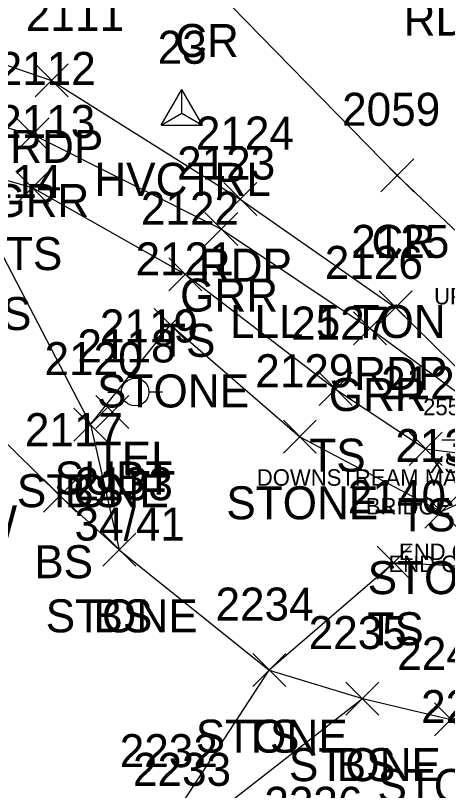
# Model space of a CAD drawing. Extents: x 1459992 to 1461532, y 647785 to 648535.
# Drawn here: x 1461256.61 to 1461282.8, y 648190.36 to 648237.31 of the extents above; entities that cross this region are included whole.
import ezdxf

# ---------------------------------------------------------------- set-up
doc = ezdxf.new("R2010")
doc.units = 0
for name, color, linetype in [('B_A', 7, 'Continuous'), ('B_C', 7, 'Continuous'), ('B_I', 7, 'Continuous'), ('B_TIC', 7, 'Continuous'), ('C_A', 7, 'Continuous'), ('C_I', 7, 'Continuous'), ('CPSM', 7, 'Continuous'), ('L_A', 7, 'Continuous'), ('L_I', 7, 'Continuous'), ('L_TIC', 7, 'Continuous'), ('LASF', 7, 'Continuous'), ('LELB', 7, 'Continuous'), ('P_A', 7, 'Continuous'), ('P_I', 7, 'Continuous'), ('P_TIC', 7, 'Continuous'), ('PET', 7, 'Continuous'), ('PRC', 7, 'Continuous'), ('R_A', 7, 'Continuous'), ('R_I', 7, 'Continuous'), ('R_TIC', 7, 'Continuous'), ('RGR', 7, 'Continuous'), ('S_C', 7, 'Continuous'), ('U_A', 7, 'Continuous'), ('U_C', 7, 'Continuous'), ('U_I', 7, 'Continuous'), ('U_TIC', 7, 'Continuous'), ('UP', 7, 'Continuous')]:
    doc.layers.add(name, color=color, linetype=linetype)

msp = doc.modelspace()

# ---------------------------------------------------------------- linework, layer by layer
at = {"layer": 'B_TIC'}
msp.add_lwpolyline([(1461282.453, 648211.596), (1461283.453, 648211.596)], dxfattribs=at)
at = {"layer": 'CPSM'}
for p, q in [((1461265.443, 648230.661), (1461266.693, 648232.827)), ((1461267.943, 648230.661), (1461266.693, 648232.827)), ((1461266.693, 648231.383), (1461266.693, 648232.827)), ((1461265.443, 648230.661), (1461266.693, 648231.383)), ((1461266.693, 648231.383), (1461266.693, 648231.383)), ((1461266.693, 648231.383), (1461267.943, 648230.661)), ((1461265.443, 648230.661), (1461267.943, 648230.661))]:
    msp.add_line(p, q, dxfattribs=at)
at = {"layer": 'L_TIC'}
for points in [[(1461256.622, 648225.885), (1461258.622, 648227.885)], [(1461258.622, 648225.885), (1461256.622, 648227.885)], [(1461265.905, 648220.633), (1461267.905, 648222.633)], [(1461267.905, 648220.633), (1461265.905, 648222.633)], [(1461265.013, 648217.565), (1461267.013, 648219.565)], [(1461267.013, 648217.565), (1461265.013, 648219.565)], [(1461275.015, 648213.676), (1461277.015, 648215.676)], [(1461277.015, 648213.676), (1461275.015, 648215.676)], [(1461260.148, 648211.524), (1461262.148, 648213.524)], [(1461262.148, 648211.524), (1461260.148, 648213.524)], [(1461260.148, 648211.524), (1461262.148, 648213.524)], [(1461262.148, 648211.524), (1461260.148, 648213.524)], [(1461260.148, 648211.524), (1461262.148, 648213.524)], [(1461262.148, 648211.524), (1461260.148, 648213.524)], [(1461272.847, 648210.789), (1461274.847, 648212.789)], [(1461274.847, 648210.789), (1461272.847, 648212.789)], [(1461280.468, 648210.059), (1461282.468, 648212.059)], [(1461282.468, 648210.059), (1461280.468, 648212.059)], [(1461258.305, 648207.22), (1461260.305, 648209.22)], [(1461260.305, 648207.22), (1461258.305, 648209.22)], [(1461281.416, 648206.257), (1461283.416, 648208.257)], [(1461283.416, 648206.257), (1461281.416, 648208.257)], [(1461261.896, 648203.943), (1461263.896, 648205.943)], [(1461263.896, 648203.943), (1461261.896, 648205.943)], [(1461261.896, 648203.943), (1461263.896, 648205.943)], [(1461263.896, 648203.943), (1461261.896, 648205.943)], [(1461278.537, 648203.161), (1461280.537, 648205.161)], [(1461280.537, 648203.161), (1461278.537, 648205.161)], [(1461270.994, 648196.654), (1461272.994, 648198.654)], [(1461272.994, 648196.654), (1461270.994, 648198.654)], [(1461270.994, 648196.654), (1461272.994, 648198.654)], [(1461272.994, 648196.654), (1461270.994, 648198.654)], [(1461270.994, 648196.654), (1461272.994, 648198.654)], [(1461272.994, 648196.654), (1461270.994, 648198.654)], [(1461276.642, 648194.929), (1461278.642, 648196.929)], [(1461278.642, 648194.929), (1461276.642, 648196.929)], [(1461276.642, 648194.929), (1461278.642, 648196.929)], [(1461278.642, 648194.929), (1461276.642, 648196.929)], [(1461282.013, 648193.668), (1461284.013, 648195.668)], [(1461284.013, 648193.668), (1461282.013, 648195.668)]]:
    msp.add_lwpolyline(points, dxfattribs=at)
at = {"layer": 'LASF'}
for points in [[(1461261.148, 648212.524), (1461266.013, 648218.565), (1461273.847, 648211.789), (1461282.416, 648207.257), (1461287.137, 648209.41), (1461289.973, 648206.761)], [(1461261.148, 648212.524), (1461262.896, 648204.943), (1461271.994, 648197.654), (1461277.642, 648195.929), (1461283.013, 648194.668), (1461287.846, 648196.16), (1461290.611, 648203.988)]]:
    msp.add_lwpolyline(points, dxfattribs=at)
at = {"layer": 'LELB'}
for points in [[(1460941.155, 648349.779), (1460973.92, 648337.195), (1461015.239, 648321.114), (1461040.673, 648310.011), (1461064.176, 648298.157), (1461082.218, 648291.361), (1461125.015, 648274.336), (1461150.746, 648265.386), (1461172.278, 648256.95), (1461198.573, 648246.423), (1461222.999, 648236.28), (1461241.79, 648231.374), (1461257.622, 648226.885), (1461266.905, 648221.633), (1461276.015, 648214.676), (1461281.468, 648211.059), (1461286.335, 648210.461)], [(1460939.639, 648344.383), (1460971.191, 648332.049), (1461012.995, 648314.771), (1461039.307, 648304.758), (1461062.903, 648294.467), (1461067.87, 648294.36), (1461073.924, 648287.11), (1461122.334, 648270.193), (1461146.573, 648259.509), (1461168.438, 648252.025), (1461196.405, 648241.557), (1461220.178, 648231.277), (1461239.026, 648226.471), (1461251, 648216.363), (1461259.305, 648208.22), (1461262.896, 648204.943)], [(1461241.79, 648231.374), (1461255.568, 648223.254), (1461261.148, 648212.524)], [(1461289.479, 648204.615), (1461285.402, 648203.847), (1461279.537, 648204.161), (1461271.994, 648197.654)], [(1461127.841, 648072.025), (1461157.366, 648076.315), (1461166.908, 648084.021), (1461183.556, 648102.817), (1461209.905, 648116.903), (1461222.502, 648127.212), (1461235.952, 648145.681), (1461248.534, 648165.182), (1461258.154, 648179.244), (1461266.186, 648188.777), (1461271.994, 648197.654)], [(1461133.589, 648067.118), (1461157.379, 648067.438), (1461176.46, 648078.839), (1461190.117, 648095.99), (1461212.044, 648111.684), (1461225.88, 648123.016), (1461241.312, 648138.966), (1461251.31, 648160.567), (1461263.44, 648174.908), (1461266.99, 648187.645), (1461277.642, 648195.929)]]:
    msp.add_lwpolyline(points, dxfattribs=at)
at = {"layer": 'P_TIC'}
for points in [[(1461257.799, 648232.378), (1461259.799, 648234.378)], [(1461259.799, 648232.378), (1461257.799, 648234.378)], [(1461278.758, 648226.625), (1461280.758, 648228.625)], [(1461280.758, 648226.625), (1461278.758, 648228.625)], [(1461269.233, 648225.186), (1461271.233, 648227.186)], [(1461271.233, 648225.186), (1461269.233, 648227.186)], [(1461278.655, 648218.625), (1461280.655, 648220.625)], [(1461280.655, 648218.625), (1461278.655, 648220.625)]]:
    msp.add_lwpolyline(points, dxfattribs=at)
at = {"layer": 'PET'}
msp.add_lwpolyline([(1460942.847, 648353.977), (1460975.344, 648340.073), (1461016.078, 648323.291), (1461041.442, 648312.663), (1461070.032, 648301.093), (1461083.953, 648295.617), (1461128.854, 648279.258), (1461164.213, 648269.583), (1461178.625, 648262.649), (1461203.087, 648251.994), (1461227.855, 648243.019), (1461244.861, 648238.131), (1461258.799, 648233.378), (1461270.233, 648226.186), (1461279.655, 648219.625), (1461287.609, 648211.808)], dxfattribs=at)
at = {"layer": 'PRC'}
msp.add_lwpolyline([(1461291.541, 648216.46), (1461279.758, 648227.625), (1461267.854, 648239.793), (1461268.374, 648256.519), (1461269.056, 648273.722), (1461275.705, 648293.856)], dxfattribs=at)
at = {"layer": 'R_TIC'}
for points in [[(1461256.651, 648229.099), (1461258.651, 648231.099)], [(1461258.651, 648229.099), (1461256.651, 648231.099)], [(1461268.097, 648223.37), (1461270.097, 648225.37)], [(1461270.097, 648223.37), (1461268.097, 648225.37)], [(1461277.109, 648217.349), (1461279.109, 648219.349)], [(1461279.109, 648217.349), (1461277.109, 648219.349)]]:
    msp.add_lwpolyline(points, dxfattribs=at)
at = {"layer": 'RGR'}
msp.add_lwpolyline([(1461241.967, 648234.202), (1461257.651, 648230.099), (1461269.097, 648224.37), (1461278.109, 648218.349), (1461287.305, 648211.601)], dxfattribs=at)
at = {"layer": 'U_TIC'}
for points in [[(1461261.488, 648212.292), (1461263.488, 648214.292)], [(1461263.488, 648212.292), (1461261.488, 648214.292)]]:
    msp.add_lwpolyline(points, dxfattribs=at)
at = {"layer": 'UP'}
for p, q in [((1461262.2, 648214.496), (1461263.026, 648214.496)), ((1461263.859, 648214.501), (1461263.859, 648214.501)), ((1461265.526, 648214.501), (1461264.692, 648214.501)), ((1461264.692, 648214.501), (1461264.692, 648214.501)), ((1461265.526, 648214.501), (1461265.526, 648214.501))]:
    msp.add_line(p, q, dxfattribs=at)
msp.add_circle((1461263.859, 648214.501), 0.833, dxfattribs=at)

# ---------------------------------------------------------------- texts
at = {"layer": 'B_A'}
msp.add_text('XSF', height=1, dxfattribs=at).set_placement((1461281.712, 648209.596))
at = {"layer": 'B_C'}
for s, p in [('UPSTREAM MAJOR SUPPORT BEAM', (1461281.986, 648219.807)), ('DOWNSTREAM MAJOR SUPPORT BEAM', (1461271.24, 648208.823)), ('BRIDGE ENTRANCE OPENING', (1461277.848, 648207.083)), ('BRIDGE ENTRANCE OPENING', (1461277.848, 648207.083)), ("END OF BEAM IS 4.2' FURTHER", (1461279.86, 648204.323)), ("END OF BEAM IS 4.2' FURTHER", (1461279.22, 648203.596))]:
    msp.add_text(s, height=1, dxfattribs=at).set_placement(p)
at = {"layer": 'B_I'}
msp.add_text('2555', height=1, dxfattribs=at).set_placement((1461281.323, 648213.096))
at = {"layer": 'C_A'}
msp.add_text('HVCTRL', height=2, dxfattribs=at).set_placement((1461261.386, 648226.383))
at = {"layer": 'C_I'}
msp.add_text('23', height=2, dxfattribs=at).set_placement((1461265.228, 648234.383))
at = {"layer": 'L_A'}
for s, p in [('TS', (1461256.031, 648221.885)), ('BS', (1461254.009, 648218.254)), ('TS', (1461265.314, 648216.633)), ('STONE', (1461261.556, 648213.565)), ('TS', (1461274.424, 648209.676)), ('STONE', (1461256.691, 648207.524)), ('STONE', (1461256.691, 648207.524)), ('BS', (1461259.589, 648207.524)), ('STONE', (1461269.39, 648206.789)), ('TS', (1461279.877, 648206.059)), ('BS', (1461257.746, 648203.22)), ('STONE', (1461277.959, 648202.257)), ('STONE', (1461258.439, 648199.943)), ('BS', (1461261.337, 648199.943)), ('TS', (1461277.947, 648199.161)), ('STONE', (1461267.537, 648192.654)), ('TS', (1461270.403, 648192.654)), ('TS', (1461270.403, 648192.654)), ('STONE', (1461273.186, 648190.929)), ('BS', (1461276.083, 648190.929)), ('STONE', (1461278.557, 648189.668))]:
    msp.add_text(s, height=2, dxfattribs=at).set_placement(p)
at = {"layer": 'L_I'}
for s, p in [('2113', (1461255.496, 648229.885)), ('2114', (1461253.442, 648226.254)), ('2122', (1461264.212, 648224.633)), ('2121', (1461263.887, 648221.565)), ('2127', (1461273.322, 648217.676)), ('2120', (1461258.368, 648215.524)), ('2120', (1461258.368, 648215.524)), ('2120', (1461258.368, 648215.524)), ('2129', (1461271.146, 648214.789)), ('2128', (1461278.775, 648214.059)), ('2117', (1461257.179, 648211.22)), ('2130', (1461279.636, 648210.257)), ('2133', (1461260.203, 648207.943)), ('2133', (1461260.203, 648207.943)), ('2140', (1461276.758, 648207.161)), ('2234', (1461268.734, 648200.654)), ('2234', (1461268.734, 648200.654)), ('2234', (1461268.734, 648200.654)), ('2235', (1461274.382, 648198.929)), ('2235', (1461274.382, 648198.929)), ('2244', (1461279.754, 648197.668)), ('2243', (1461281.199, 648194.448)), ('2243', (1461281.199, 648194.448)), ('2232', (1461262.926, 648191.777)), ('2233', (1461263.73, 648190.645)), ('2236', (1461271.695, 648188.587))]:
    msp.add_text(s, height=2, dxfattribs=at).set_placement(p)
at = {"layer": 'P_A'}
for s, p in [('RDP', (1461280.141, 648236.085)), ('CR', (1461266.287, 648234.793)), ('CR', (1461266.287, 648234.793)), ('RDP', (1461256.287, 648228.378)), ('CR', (1461278.191, 648222.625)), ('RDP', (1461267.722, 648221.186)), ('RDP', (1461277.143, 648214.625))]:
    msp.add_text(s, height=2, dxfattribs=at).set_placement(p)
at = {"layer": 'P_I'}
for s, p in [('2111', (1461257.24, 648236.378)), ('2059', (1461276.411, 648230.625)), ('2124', (1461267.541, 648229.186)), ('2125', (1461276.962, 648222.625))]:
    msp.add_text(s, height=2, dxfattribs=at).set_placement(p)
at = {"layer": 'R_A'}
for p in [(1461255.139, 648225.099), (1461266.585, 648219.37), (1461275.597, 648213.349)]:
    msp.add_text('GRR', height=2, dxfattribs=at).set_placement(p)
at = {"layer": 'R_I'}
for s, p in [('2112', (1461255.525, 648233.099)), ('2123', (1461266.404, 648227.37)), ('2126', (1461275.361, 648221.349))]:
    msp.add_text(s, height=2, dxfattribs=at).set_placement(p)
at = {"layer": 'S_C'}
msp.add_text('LLL 5 TON HEIGHT CLEARANCE', height=2, dxfattribs=at).set_placement((1461269.609, 648217.773))
at = {"layer": 'U_A'}
for s, p in [('TEL', (1461261.418, 648209.501)), ('SUBT', (1461258.985, 648208.292)), ('GUYW', (1461248.389, 648205.638))]:
    msp.add_text(s, height=2, dxfattribs=at).set_placement(p)
at = {"layer": 'U_C'}
msp.add_text('34/41', height=2, dxfattribs=at).set_placement((1461260.19, 648205.501))
at = {"layer": 'U_I'}
for s, p in [('2119', (1461261.725, 648217.501)), ('2118', (1461260.362, 648216.292))]:
    msp.add_text(s, height=2, dxfattribs=at).set_placement(p)

doc.saveas('drawing.dxf')
